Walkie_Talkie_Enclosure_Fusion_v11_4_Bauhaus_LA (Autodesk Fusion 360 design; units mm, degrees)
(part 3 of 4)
sketch "PTT Interaction Field Sketch" plane through (0, 0, 0) normal (1, 0, 0) x axis (0, 0, -1)
  line L1 (-14.65, -17.5) -> (-14.85, -17.5)
  line L2 (-7.85, 34.7) -> (-7.85, -10.7)
  line L3 (-14.85, 41.5) -> (-14.65, 41.5)
  line L4 (-21.65, -10.7) -> (-21.65, 34.7)
  arc A1 centre (-14.65, -10.7) radius 6.8 clockwise from (-7.85, -10.7) to (-14.65, -17.5)
  arc A2 centre (-14.65, 34.7) radius 6.8 clockwise from (-14.65, 41.5) to (-7.85, 34.7)
  arc A3 centre (-14.85, 34.7) radius 6.8 clockwise from (-21.65, 34.7) to (-14.85, 41.5)
  arc A4 centre (-14.85, -10.7) radius 6.8 clockwise from (-14.85, -17.5) to (-21.65, -10.7)
extrude "Extrude7" cut sketch "PTT Interaction Field Sketch" blind -0.42 (= "-( 0.42 mm )") from offset 39.2
sketch "Unified Volume Interaction Field Sketch" plane through (0, 0, 0) normal (1, 0, 0) x axis (0, 0, -1)
  line L1 (-14.65, -21.25) -> (-14.85, -21.25)
  line L2 (-7.85, 31.45) -> (-7.85, -14.45)
  line L3 (-14.85, 38.25) -> (-14.65, 38.25)
  line L4 (-21.65, -14.45) -> (-21.65, 31.45)
  arc A1 centre (-14.65, -14.45) radius 6.8 clockwise from (-7.85, -14.45) to (-14.65, -21.25)
  arc A2 centre (-14.65, 31.45) radius 6.8 clockwise from (-14.65, 38.25) to (-7.85, 31.45)
  arc A3 centre (-14.85, 31.45) radius 6.8 clockwise from (-21.65, 31.45) to (-14.85, 38.25)
  arc A4 centre (-14.85, -14.45) radius 6.8 clockwise from (-14.85, -21.25) to (-21.65, -14.45)
extrude "Extrude8" cut sketch "Unified Volume Interaction Field Sketch" blind 0.42 from offset -39.2
sketch "Left PTT Through Opening Sketch" plane through (0, 0, 0) normal (1, 0, 0) x axis (0, 0, -1)
  line L1 (-14.65, -13.2) -> (-14.85, -13.2)
  line L2 (-10.25, 32.8) -> (-10.25, -8.8)
  line L3 (-14.85, 37.2) -> (-14.65, 37.2)
  line L4 (-19.25, -8.8) -> (-19.25, 32.8)
  arc A1 centre (-14.65, -8.8) radius 4.4 clockwise from (-10.25, -8.8) to (-14.65, -13.2)
  arc A2 centre (-14.65, 32.8) radius 4.4 clockwise from (-14.65, 37.2) to (-10.25, 32.8)
  arc A3 centre (-14.85, 32.8) radius 4.4 clockwise from (-19.25, 32.8) to (-14.85, 37.2)
  arc A4 centre (-14.85, -8.8) radius 4.4 clockwise from (-14.85, -13.2) to (-19.25, -8.8)
extrude "Extrude9" cut sketch "Left PTT Through Opening Sketch" blind 40
sketch "Volume Up Through Opening Sketch" plane through (0, 0, 0) normal (1, 0, 0) x axis (0, 0, -1)
  line L1 (-14.65, 15.15) -> (-14.85, 15.15)
  line L2 (-10.55, 26.75) -> (-10.55, 19.25)
  line L3 (-14.85, 30.85) -> (-14.65, 30.85)
  line L4 (-18.95, 19.25) -> (-18.95, 26.75)
  arc A1 centre (-14.65, 19.25) radius 4.1 clockwise from (-10.55, 19.25) to (-14.65, 15.15)
  arc A2 centre (-14.65, 26.75) radius 4.1 clockwise from (-14.65, 30.85) to (-10.55, 26.75)
  arc A3 centre (-14.85, 26.75) radius 4.1 clockwise from (-18.95, 26.75) to (-14.85, 30.85)
  arc A4 centre (-14.85, 19.25) radius 4.1 clockwise from (-14.85, 15.15) to (-18.95, 19.25)
extrude "Extrude10" cut sketch "Volume Up Through Opening Sketch" blind -40 (= "-( 40.00 mm )")
sketch "Volume Down Through Opening Sketch" plane through (0, 0, 0) normal (1, 0, 0) x axis (0, 0, -1)
  line L1 (-14.65, -13.85) -> (-14.85, -13.85)
  line L2 (-10.55, -2.25) -> (-10.55, -9.75)
  line L3 (-14.85, 1.85) -> (-14.65, 1.85)
  line L4 (-18.95, -9.75) -> (-18.95, -2.25)
  arc A1 centre (-14.65, -9.75) radius 4.1 clockwise from (-10.55, -9.75) to (-14.65, -13.85)
  arc A2 centre (-14.65, -2.25) radius 4.1 clockwise from (-14.65, 1.85) to (-10.55, -2.25)
  arc A3 centre (-14.85, -2.25) radius 4.1 clockwise from (-18.95, -2.25) to (-14.85, 1.85)
  arc A4 centre (-14.85, -9.75) radius 4.1 clockwise from (-14.85, -13.85) to (-18.95, -9.75)
extrude "Extrude11" cut sketch "Volume Down Through Opening Sketch" blind -40 (= "-( 40.00 mm )")
sketch "USB-C Full-Seating Local Wall Recess Sketch" plane through (0, 0, 0) normal (1, 0, 0) x axis (0, 0, -1)
  line L1 (-12.4264, -27.6393) -> (-12.9264, -27.6393)
  line L2 (-8.9764, -17.8393) -> (-8.9764, -24.1893)
  line L3 (-12.9264, -14.3893) -> (-12.4264, -14.3893)
  line L4 (-16.3764, -24.1893) -> (-16.3764, -17.8393)
  arc A1 centre (-12.4264, -24.1893) radius 3.45 clockwise from (-8.9764, -24.1893) to (-12.4264, -27.6393)
  arc A2 centre (-12.4264, -17.8393) radius 3.45 clockwise from (-12.4264, -14.3893) to (-8.9764, -17.8393)
  arc A3 centre (-12.9264, -17.8393) radius 3.45 clockwise from (-16.3764, -17.8393) to (-12.9264, -14.3893)
  arc A4 centre (-12.9264, -24.1893) radius 3.45 clockwise from (-12.9264, -27.6393) to (-16.3764, -24.1893)
extrude "Extrude12" cut sketch "USB-C Full-Seating Local Wall Recess Sketch" blind -2.9527 (= "-( 2.952733 mm )") from offset 39.2
sketch "Sketch13" plane through (0, 0, 0) normal (1, 0, 0) x axis (0, 0, -1)
  line L1 (-12.6264, -25.7043) -> (-12.7264, -25.7043)
  line L2 (-10.2799, -18.6708) -> (-10.2799, -23.3578)
  line L3 (-12.7264, -16.3243) -> (-12.6264, -16.3243)
  line L4 (-15.0729, -23.3578) -> (-15.0729, -18.6708)
  arc A1 centre (-12.6264, -23.3578) radius 2.3465 clockwise from (-10.2799, -23.3578) to (-12.6264, -25.7043)
  arc A2 centre (-12.6264, -18.6708) radius 2.3465 clockwise from (-12.6264, -16.3243) to (-10.2799, -18.6708)
  arc A3 centre (-12.7264, -18.6708) radius 2.3465 clockwise from (-15.0729, -18.6708) to (-12.7264, -16.3243)
  arc A4 centre (-12.7264, -23.3578) radius 2.3465 clockwise from (-12.7264, -25.7043) to (-15.0729, -23.3578)
extrude "Extrude13" cut sketch "Sketch13" blind 40
sketch "PTT Internal Switch Body Clearance Sketch" plane through (0, 0, 0) normal (1, 0, 0) x axis (0, 0, -1)
  line L1 (-10, 6.65) -> (-19.5, 6.65)
  line L2 (-9.55, 16.9) -> (-9.55, 7.1)
  line L3 (-19.5, 17.35) -> (-10, 17.35)
  line L4 (-19.95, 7.1) -> (-19.95, 16.9)
  arc A1 centre (-10, 7.1) radius 0.45 clockwise from (-9.55, 7.1) to (-10, 6.65)
  arc A2 centre (-10, 16.9) radius 0.45 clockwise from (-10, 17.35) to (-9.55, 16.9)
  arc A3 centre (-19.5, 16.9) radius 0.45 clockwise from (-19.95, 16.9) to (-19.5, 17.35)
  arc A4 centre (-19.5, 7.1) radius 0.45 clockwise from (-19.5, 6.65) to (-19.95, 7.1)
extrude "Extrude14" cut sketch "PTT Internal Switch Body Clearance Sketch" blind 5.1 from offset 31.9
sketch "PTT Switch Cage Anchor Sketch" plane through (0, 0, 0) normal (0, 0, 1) x axis (1, 0, 0)
  line L1 (32, 6.45) -> (31.5, 6.45)
  line L2 (32.35, 7.3) -> (32.35, 6.8)
  line L3 (31.5, 7.65) -> (32, 7.65)
  line L4 (31.15, 6.8) -> (31.15, 7.3)
  arc A1 centre (32, 6.8) radius 0.35 clockwise from (32.35, 6.8) to (32, 6.45)
  arc A2 centre (32, 7.3) radius 0.35 clockwise from (32, 7.65) to (32.35, 7.3)
  arc A3 centre (31.5, 7.3) radius 0.35 clockwise from (31.15, 7.3) to (31.5, 7.65)
  arc A4 centre (31.5, 6.8) radius 0.35 clockwise from (31.5, 6.45) to (31.15, 6.8)
extrude "Extrude15" add sketch "PTT Switch Cage Anchor Sketch" blind 7.3 from offset 20.15
sketch "PTT Switch Cage Anchor Sketch (1)" plane through (0, 0, 0) normal (0, 0, 1) x axis (1, 0, 0)
  line L1 (32, 16.35) -> (31.5, 16.35)
  line L2 (32.35, 17.2) -> (32.35, 16.7)
  line L3 (31.5, 17.55) -> (32, 17.55)
  line L4 (31.15, 16.7) -> (31.15, 17.2)
  arc A1 centre (32, 16.7) radius 0.35 clockwise from (32.35, 16.7) to (32, 16.35)
  arc A2 centre (32, 17.2) radius 0.35 clockwise from (32, 17.55) to (32.35, 17.2)
  arc A3 centre (31.5, 17.2) radius 0.35 clockwise from (31.15, 17.2) to (31.5, 17.55)
  arc A4 centre (31.5, 16.7) radius 0.35 clockwise from (31.5, 16.35) to (31.15, 16.7)
extrude "Extrude16" add sketch "PTT Switch Cage Anchor Sketch (1)" blind 7.3 from offset 20.15
sketch "PTT Switch Roof Sketch" plane through (0, 0, 0) normal (0, 0, 1) x axis (1, 0, 0)
  line L1 (36.45, 6.65) -> (31.75, 6.65)
  line L2 (36.9, 16.9) -> (36.9, 7.1)
  line L3 (31.75, 17.35) -> (36.45, 17.35)
  line L4 (31.3, 7.1) -> (31.3, 16.9)
  arc A1 centre (36.45, 7.1) radius 0.45 clockwise from (36.9, 7.1) to (36.45, 6.65)
  arc A2 centre (36.45, 16.9) radius 0.45 clockwise from (36.45, 17.35) to (36.9, 16.9)
  arc A3 centre (31.75, 16.9) radius 0.45 clockwise from (31.3, 16.9) to (31.75, 17.35)
  arc A4 centre (31.75, 7.1) radius 0.45 clockwise from (31.75, 6.65) to (31.3, 7.1)
extrude "Extrude17" add sketch "PTT Switch Roof Sketch" blind 0.55 from offset 19.7
sketch "PTT Switch Inward Backstop Sketch" plane through (0, 0, 0) normal (0, 0, 1) x axis (1, 0, 0)
  line L1 (31.85, 6.65) -> (31.65, 6.65)
  line L2 (32.2, 17) -> (32.2, 7)
  line L3 (31.65, 17.35) -> (31.85, 17.35)
  line L4 (31.3, 7) -> (31.3, 17)
  arc A1 centre (31.85, 7) radius 0.35 clockwise from (32.2, 7) to (31.85, 6.65)
  arc A2 centre (31.85, 17) radius 0.35 clockwise from (31.85, 17.35) to (32.2, 17)
  arc A3 centre (31.65, 17) radius 0.35 clockwise from (31.3, 17) to (31.65, 17.35)
  arc A4 centre (31.65, 7) radius 0.35 clockwise from (31.65, 6.65) to (31.3, 7)
extrude "Extrude18" add sketch "PTT Switch Inward Backstop Sketch" blind 5.25 from offset 15
sketch "PTT Switch Side Rail Sketch" plane through (0, 0, 0) normal (0, 0, 1) x axis (1, 0, 0)
  line L1 (36.675, 6.65) -> (32.325, 6.65)
  line L2 (36.975, 7.15) -> (36.975, 6.95)
  line L3 (32.325, 7.45) -> (36.675, 7.45)
  line L4 (32.025, 6.95) -> (32.025, 7.15)
  arc A1 centre (36.675, 6.95) radius 0.3 clockwise from (36.975, 6.95) to (36.675, 6.65)
  arc A2 centre (36.675, 7.15) radius 0.3 clockwise from (36.675, 7.45) to (36.975, 7.15)
  arc A3 centre (32.325, 7.15) radius 0.3 clockwise from (32.025, 7.15) to (32.325, 7.45)
  arc A4 centre (32.325, 6.95) radius 0.3 clockwise from (32.325, 6.65) to (32.025, 6.95)
extrude "Extrude19" add sketch "PTT Switch Side Rail Sketch" blind 5.25 from offset 15
sketch "PTT Switch Side Rail Sketch (1)" plane through (0, 0, 0) normal (0, 0, 1) x axis (1, 0, 0)
  line L1 (36.675, 16.55) -> (32.325, 16.55)
  line L2 (36.975, 17.05) -> (36.975, 16.85)
  line L3 (32.325, 17.35) -> (36.675, 17.35)
  line L4 (32.025, 16.85) -> (32.025, 17.05)
  arc A1 centre (36.675, 16.85) radius 0.3 clockwise from (36.975, 16.85) to (36.675, 16.55)
  arc A2 centre (36.675, 17.05) radius 0.3 clockwise from (36.675, 17.35) to (36.975, 17.05)
  arc A3 centre (32.325, 17.05) radius 0.3 clockwise from (32.025, 17.05) to (32.325, 17.35)
  arc A4 centre (32.325, 16.85) radius 0.3 clockwise from (32.325, 16.55) to (32.025, 16.85)
extrude "Extrude20" add sketch "PTT Switch Side Rail Sketch (1)" blind 5.25 from offset 15
sketch "PTT Switch Actuator Shoulder Sketch" plane through (0, 0, 0) normal (0, 0, 1) x axis (1, 0, 0)
  line L1 (37.28, 6.65) -> (37.22, 6.65)
  line L2 (37.5, 17.13) -> (37.5, 6.87)
  line L3 (37.22, 17.35) -> (37.28, 17.35)
  line L4 (37, 6.87) -> (37, 17.13)
  arc A1 centre (37.28, 6.87) radius 0.22 clockwise from (37.5, 6.87) to (37.28, 6.65)
  arc A2 centre (37.28, 17.13) radius 0.22 clockwise from (37.28, 17.35) to (37.5, 17.13)
  arc A3 centre (37.22, 17.13) radius 0.22 clockwise from (37, 17.13) to (37.22, 17.35)
  arc A4 centre (37.22, 6.87) radius 0.22 clockwise from (37.22, 6.65) to (37, 6.87)
extrude "Extrude21" add sketch "PTT Switch Actuator Shoulder Sketch" blind 5.25 from offset 15
sketch "PTT Actuator Passage Sketch" plane through (0, 0, 0) normal (1, 0, 0) x axis (0, 0, -1)
  line L1 (-15.9, 10.6) -> (-17.5, 10.6)
  line L2 (-15.3, 12.8) -> (-15.3, 11.2)
  line L3 (-17.5, 13.4) -> (-15.9, 13.4)
  line L4 (-18.1, 11.2) -> (-18.1, 12.8)
  arc A1 centre (-15.9, 11.2) radius 0.6 clockwise from (-15.3, 11.2) to (-15.9, 10.6)
  arc A2 centre (-15.9, 12.8) radius 0.6 clockwise from (-15.9, 13.4) to (-15.3, 12.8)
  arc A3 centre (-17.5, 12.8) radius 0.6 clockwise from (-18.1, 12.8) to (-17.5, 13.4)
  arc A4 centre (-17.5, 11.2) radius 0.6 clockwise from (-17.5, 10.6) to (-18.1, 11.2)
extrude "Extrude22" cut sketch "PTT Actuator Passage Sketch" blind 1.9 from offset 35.8
sketch "Volume Up Internal Switch Body Clearance Sketch" plane through (0, 0, 0) normal (1, 0, 0) x axis (0, 0, -1)
  line L1 (-10, 17.65) -> (-19.5, 17.65)
  line L2 (-9.55, 27.9) -> (-9.55, 18.1)
  line L3 (-19.5, 28.35) -> (-10, 28.35)
  line L4 (-19.95, 18.1) -> (-19.95, 27.9)
  arc A1 centre (-10, 18.1) radius 0.45 clockwise from (-9.55, 18.1) to (-10, 17.65)
  arc A2 centre (-10, 27.9) radius 0.45 clockwise from (-10, 28.35) to (-9.55, 27.9)
  arc A3 centre (-19.5, 27.9) radius 0.45 clockwise from (-19.95, 27.9) to (-19.5, 28.35)
  arc A4 centre (-19.5, 18.1) radius 0.45 clockwise from (-19.5, 17.65) to (-19.95, 18.1)
extrude "Extrude23" cut sketch "Volume Up Internal Switch Body Clearance Sketch" blind -5.1 (= "-( 5.10 mm )") from offset -31.9
sketch "Volume Up Switch Cage Anchor Sketch" plane through (0, 0, 0) normal (0, 0, 1) x axis (1, 0, 0)
  line L1 (-31.5, 17.45) -> (-32, 17.45)
  line L2 (-31.15, 18.3) -> (-31.15, 17.8)
  line L3 (-32, 18.65) -> (-31.5, 18.65)
  line L4 (-32.35, 17.8) -> (-32.35, 18.3)
  arc A1 centre (-31.5, 17.8) radius 0.35 clockwise from (-31.15, 17.8) to (-31.5, 17.45)
  arc A2 centre (-31.5, 18.3) radius 0.35 clockwise from (-31.5, 18.65) to (-31.15, 18.3)
  arc A3 centre (-32, 18.3) radius 0.35 clockwise from (-32.35, 18.3) to (-32, 18.65)
  arc A4 centre (-32, 17.8) radius 0.35 clockwise from (-32, 17.45) to (-32.35, 17.8)
extrude "Extrude24" add sketch "Volume Up Switch Cage Anchor Sketch" blind 7.3 from offset 20.15
sketch "Volume Up Switch Cage Anchor Sketch (1)" plane through (0, 0, 0) normal (0, 0, 1) x axis (1, 0, 0)
  line L1 (-31.5, 27.35) -> (-32, 27.35)
  line L2 (-31.15, 28.2) -> (-31.15, 27.7)
  line L3 (-32, 28.55) -> (-31.5, 28.55)
  line L4 (-32.35, 27.7) -> (-32.35, 28.2)
  arc A1 centre (-31.5, 27.7) radius 0.35 clockwise from (-31.15, 27.7) to (-31.5, 27.35)
  arc A2 centre (-31.5, 28.2) radius 0.35 clockwise from (-31.5, 28.55) to (-31.15, 28.2)
  arc A3 centre (-32, 28.2) radius 0.35 clockwise from (-32.35, 28.2) to (-32, 28.55)
  arc A4 centre (-32, 27.7) radius 0.35 clockwise from (-32, 27.35) to (-32.35, 27.7)
extrude "Extrude25" add sketch "Volume Up Switch Cage Anchor Sketch (1)" blind 7.3 from offset 20.15
sketch "Volume Up Switch Roof Sketch" plane through (0, 0, 0) normal (0, 0, 1) x axis (1, 0, 0)
  line L1 (-31.75, 17.65) -> (-36.45, 17.65)
  line L2 (-31.3, 27.9) -> (-31.3, 18.1)
  line L3 (-36.45, 28.35) -> (-31.75, 28.35)
  line L4 (-36.9, 18.1) -> (-36.9, 27.9)
  arc A1 centre (-31.75, 18.1) radius 0.45 clockwise from (-31.3, 18.1) to (-31.75, 17.65)
  arc A2 centre (-31.75, 27.9) radius 0.45 clockwise from (-31.75, 28.35) to (-31.3, 27.9)
  arc A3 centre (-36.45, 27.9) radius 0.45 clockwise from (-36.9, 27.9) to (-36.45, 28.35)
  arc A4 centre (-36.45, 18.1) radius 0.45 clockwise from (-36.45, 17.65) to (-36.9, 18.1)
extrude "Extrude26" add sketch "Volume Up Switch Roof Sketch" blind 0.55 from offset 19.7
sketch "Volume Up Switch Inward Backstop Sketch" plane through (0, 0, 0) normal (0, 0, 1) x axis (1, 0, 0)
  line L1 (-31.65, 17.65) -> (-31.85, 17.65)
  line L2 (-31.3, 28) -> (-31.3, 18)
  line L3 (-31.85, 28.35) -> (-31.65, 28.35)
  line L4 (-32.2, 18) -> (-32.2, 28)
  arc A1 centre (-31.65, 18) radius 0.35 clockwise from (-31.3, 18) to (-31.65, 17.65)
  arc A2 centre (-31.65, 28) radius 0.35 clockwise from (-31.65, 28.35) to (-31.3, 28)
  arc A3 centre (-31.85, 28) radius 0.35 clockwise from (-32.2, 28) to (-31.85, 28.35)
  arc A4 centre (-31.85, 18) radius 0.35 clockwise from (-31.85, 17.65) to (-32.2, 18)
extrude "Extrude27" add sketch "Volume Up Switch Inward Backstop Sketch" blind 5.25 from offset 15
sketch "Volume Up Switch Side Rail Sketch" plane through (0, 0, 0) normal (0, 0, 1) x axis (1, 0, 0)
  line L1 (-32.325, 17.65) -> (-36.675, 17.65)
  line L2 (-32.025, 18.15) -> (-32.025, 17.95)
  line L3 (-36.675, 18.45) -> (-32.325, 18.45)
  line L4 (-36.975, 17.95) -> (-36.975, 18.15)
  arc A1 centre (-32.325, 17.95) radius 0.3 clockwise from (-32.025, 17.95) to (-32.325, 17.65)
  arc A2 centre (-32.325, 18.15) radius 0.3 clockwise from (-32.325, 18.45) to (-32.025, 18.15)
  arc A3 centre (-36.675, 18.15) radius 0.3 clockwise from (-36.975, 18.15) to (-36.675, 18.45)
  arc A4 centre (-36.675, 17.95) radius 0.3 clockwise from (-36.675, 17.65) to (-36.975, 17.95)
extrude "Extrude28" add sketch "Volume Up Switch Side Rail Sketch" blind 5.25 from offset 15
sketch "Volume Up Switch Side Rail Sketch (1)" plane through (0, 0, 0) normal (0, 0, 1) x axis (1, 0, 0)
  line L1 (-32.325, 27.55) -> (-36.675, 27.55)
  line L2 (-32.025, 28.05) -> (-32.025, 27.85)
  line L3 (-36.675, 28.35) -> (-32.325, 28.35)
  line L4 (-36.975, 27.85) -> (-36.975, 28.05)
  arc A1 centre (-32.325, 27.85) radius 0.3 clockwise from (-32.025, 27.85) to (-32.325, 27.55)
  arc A2 centre (-32.325, 28.05) radius 0.3 clockwise from (-32.325, 28.35) to (-32.025, 28.05)
  arc A3 centre (-36.675, 28.05) radius 0.3 clockwise from (-36.975, 28.05) to (-36.675, 28.35)
  arc A4 centre (-36.675, 27.85) radius 0.3 clockwise from (-36.675, 27.55) to (-36.975, 27.85)
extrude "Extrude29" add sketch "Volume Up Switch Side Rail Sketch (1)" blind 5.25 from offset 15
sketch "Volume Up Switch Actuator Shoulder Sketch" plane through (0, 0, 0) normal (0, 0, 1) x axis (1, 0, 0)
  line L1 (-37.22, 17.65) -> (-37.28, 17.65)
  line L2 (-37, 28.13) -> (-37, 17.87)
  line L3 (-37.28, 28.35) -> (-37.22, 28.35)
  line L4 (-37.5, 17.87) -> (-37.5, 28.13)
  arc A1 centre (-37.22, 17.87) radius 0.22 clockwise from (-37, 17.87) to (-37.22, 17.65)
  arc A2 centre (-37.22, 28.13) radius 0.22 clockwise from (-37.22, 28.35) to (-37, 28.13)
  arc A3 centre (-37.28, 28.13) radius 0.22 clockwise from (-37.5, 28.13) to (-37.28, 28.35)
  arc A4 centre (-37.28, 17.87) radius 0.22 clockwise from (-37.28, 17.65) to (-37.5, 17.87)
extrude "Extrude30" add sketch "Volume Up Switch Actuator Shoulder Sketch" blind 5.25 from offset 15
sketch "Volume Up Actuator Passage Sketch" plane through (0, 0, 0) normal (1, 0, 0) x axis (0, 0, -1)
  line L1 (-15.9, 21.6) -> (-17.5, 21.6)
  line L2 (-15.3, 23.8) -> (-15.3, 22.2)
  line L3 (-17.5, 24.4) -> (-15.9, 24.4)
  line L4 (-18.1, 22.2) -> (-18.1, 23.8)
  arc A1 centre (-15.9, 22.2) radius 0.6 clockwise from (-15.3, 22.2) to (-15.9, 21.6)
  arc A2 centre (-15.9, 23.8) radius 0.6 clockwise from (-15.9, 24.4) to (-15.3, 23.8)
  arc A3 centre (-17.5, 23.8) radius 0.6 clockwise from (-18.1, 23.8) to (-17.5, 24.4)
  arc A4 centre (-17.5, 22.2) radius 0.6 clockwise from (-17.5, 21.6) to (-18.1, 22.2)
extrude "Extrude31" cut sketch "Volume Up Actuator Passage Sketch" blind -1.9 (= "-( 1.90 mm )") from offset -35.8
sketch "Volume Down Internal Switch Body Clearance Sketch" plane through (0, 0, 0) normal (1, 0, 0) x axis (0, 0, -1)
  line L1 (-10, -11.35) -> (-19.5, -11.35)
  line L2 (-9.55, -1.1) -> (-9.55, -10.9)
  line L3 (-19.5, -0.65) -> (-10, -0.65)
  line L4 (-19.95, -10.9) -> (-19.95, -1.1)
  arc A1 centre (-10, -10.9) radius 0.45 clockwise from (-9.55, -10.9) to (-10, -11.35)
  arc A2 centre (-10, -1.1) radius 0.45 clockwise from (-10, -0.65) to (-9.55, -1.1)
  arc A3 centre (-19.5, -1.1) radius 0.45 clockwise from (-19.95, -1.1) to (-19.5, -0.65)
  arc A4 centre (-19.5, -10.9) radius 0.45 clockwise from (-19.5, -11.35) to (-19.95, -10.9)
extrude "Extrude32" cut sketch "Volume Down Internal Switch Body Clearance Sketch" blind -5.1 (= "-( 5.10 mm )") from offset -31.9
sketch "Volume Down Switch Cage Anchor Sketch" plane through (0, 0, 0) normal (0, 0, 1) x axis (1, 0, 0)
  line L1 (-31.5, -11.55) -> (-32, -11.55)
  line L2 (-31.15, -10.7) -> (-31.15, -11.2)
  line L3 (-32, -10.35) -> (-31.5, -10.35)
  line L4 (-32.35, -11.2) -> (-32.35, -10.7)
  arc A1 centre (-31.5, -11.2) radius 0.35 clockwise from (-31.15, -11.2) to (-31.5, -11.55)
  arc A2 centre (-31.5, -10.7) radius 0.35 clockwise from (-31.5, -10.35) to (-31.15, -10.7)
  arc A3 centre (-32, -10.7) radius 0.35 clockwise from (-32.35, -10.7) to (-32, -10.35)
  arc A4 centre (-32, -11.2) radius 0.35 clockwise from (-32, -11.55) to (-32.35, -11.2)
extrude "Extrude33" add sketch "Volume Down Switch Cage Anchor Sketch" blind 7.3 from offset 20.15
sketch "Volume Down Switch Cage Anchor Sketch (1)" plane through (0, 0, 0) normal (0, 0, 1) x axis (1, 0, 0)
  line L1 (-31.5, -1.65) -> (-32, -1.65)
  line L2 (-31.15, -0.8) -> (-31.15, -1.3)
  line L3 (-32, -0.45) -> (-31.5, -0.45)
  line L4 (-32.35, -1.3) -> (-32.35, -0.8)
  arc A1 centre (-31.5, -1.3) radius 0.35 clockwise from (-31.15, -1.3) to (-31.5, -1.65)
  arc A2 centre (-31.5, -0.8) radius 0.35 clockwise from (-31.5, -0.45) to (-31.15, -0.8)
  arc A3 centre (-32, -0.8) radius 0.35 clockwise from (-32.35, -0.8) to (-32, -0.45)
  arc A4 centre (-32, -1.3) radius 0.35 clockwise from (-32, -1.65) to (-32.35, -1.3)
extrude "Extrude34" add sketch "Volume Down Switch Cage Anchor Sketch (1)" blind 7.3 from offset 20.15
sketch "Volume Down Switch Roof Sketch" plane through (0, 0, 0) normal (0, 0, 1) x axis (1, 0, 0)
  line L1 (-31.75, -11.35) -> (-36.45, -11.35)
  line L2 (-31.3, -1.1) -> (-31.3, -10.9)
  line L3 (-36.45, -0.65) -> (-31.75, -0.65)
  line L4 (-36.9, -10.9) -> (-36.9, -1.1)
  arc A1 centre (-31.75, -10.9) radius 0.45 clockwise from (-31.3, -10.9) to (-31.75, -11.35)
  arc A2 centre (-31.75, -1.1) radius 0.45 clockwise from (-31.75, -0.65) to (-31.3, -1.1)
  arc A3 centre (-36.45, -1.1) radius 0.45 clockwise from (-36.9, -1.1) to (-36.45, -0.65)
  arc A4 centre (-36.45, -10.9) radius 0.45 clockwise from (-36.45, -11.35) to (-36.9, -10.9)
extrude "Extrude35" add sketch "Volume Down Switch Roof Sketch" blind 0.55 from offset 19.7
sketch "Volume Down Switch Inward Backstop Sketch" plane through (0, 0, 0) normal (0, 0, 1) x axis (1, 0, 0)
  line L1 (-31.65, -11.35) -> (-31.85, -11.35)
  line L2 (-31.3, -1) -> (-31.3, -11)
  line L3 (-31.85, -0.65) -> (-31.65, -0.65)
  line L4 (-32.2, -11) -> (-32.2, -1)
  arc A1 centre (-31.65, -11) radius 0.35 clockwise from (-31.3, -11) to (-31.65, -11.35)
  arc A2 centre (-31.65, -1) radius 0.35 clockwise from (-31.65, -0.65) to (-31.3, -1)
  arc A3 centre (-31.85, -1) radius 0.35 clockwise from (-32.2, -1) to (-31.85, -0.65)
  arc A4 centre (-31.85, -11) radius 0.35 clockwise from (-31.85, -11.35) to (-32.2, -11)
extrude "Extrude36" add sketch "Volume Down Switch Inward Backstop Sketch" blind 5.25 from offset 15
sketch "Volume Down Switch Side Rail Sketch" plane through (0, 0, 0) normal (0, 0, 1) x axis (1, 0, 0)
  line L1 (-32.325, -11.35) -> (-36.675, -11.35)
  line L2 (-32.025, -10.85) -> (-32.025, -11.05)
  line L3 (-36.675, -10.55) -> (-32.325, -10.55)
  line L4 (-36.975, -11.05) -> (-36.975, -10.85)
  arc A1 centre (-32.325, -11.05) radius 0.3 clockwise from (-32.025, -11.05) to (-32.325, -11.35)
  arc A2 centre (-32.325, -10.85) radius 0.3 clockwise from (-32.325, -10.55) to (-32.025, -10.85)
  arc A3 centre (-36.675, -10.85) radius 0.3 clockwise from (-36.975, -10.85) to (-36.675, -10.55)
  arc A4 centre (-36.675, -11.05) radius 0.3 clockwise from (-36.675, -11.35) to (-36.975, -11.05)
extrude "Extrude37" add sketch "Volume Down Switch Side Rail Sketch" blind 5.25 from offset 15
sketch "Volume Down Switch Side Rail Sketch (1)" plane through (0, 0, 0) normal (0, 0, 1) x axis (1, 0, 0)
  line L1 (-32.325, -1.45) -> (-36.675, -1.45)
  line L2 (-32.025, -0.95) -> (-32.025, -1.15)
  line L3 (-36.675, -0.65) -> (-32.325, -0.65)
  line L4 (-36.975, -1.15) -> (-36.975, -0.95)
  arc A1 centre (-32.325, -1.15) radius 0.3 clockwise from (-32.025, -1.15) to (-32.325, -1.45)
  arc A2 centre (-32.325, -0.95) radius 0.3 clockwise from (-32.325, -0.65) to (-32.025, -0.95)
  arc A3 centre (-36.675, -0.95) radius 0.3 clockwise from (-36.975, -0.95) to (-36.675, -0.65)
  arc A4 centre (-36.675, -1.15) radius 0.3 clockwise from (-36.675, -1.45) to (-36.975, -1.15)
extrude "Extrude38" add sketch "Volume Down Switch Side Rail Sketch (1)" blind 5.25 from offset 15
sketch "Volume Down Switch Actuator Shoulder Sketch" plane through (0, 0, 0) normal (0, 0, 1) x axis (1, 0, 0)
  line L1 (-37.22, -11.35) -> (-37.28, -11.35)
  line L2 (-37, -0.87) -> (-37, -11.13)
  line L3 (-37.28, -0.65) -> (-37.22, -0.65)
  line L4 (-37.5, -11.13) -> (-37.5, -0.87)
  arc A1 centre (-37.22, -11.13) radius 0.22 clockwise from (-37, -11.13) to (-37.22, -11.35)
  arc A2 centre (-37.22, -0.87) radius 0.22 clockwise from (-37.22, -0.65) to (-37, -0.87)
  arc A3 centre (-37.28, -0.87) radius 0.22 clockwise from (-37.5, -0.87) to (-37.28, -0.65)
  arc A4 centre (-37.28, -11.13) radius 0.22 clockwise from (-37.28, -11.35) to (-37.5, -11.13)
extrude "Extrude39" add sketch "Volume Down Switch Actuator Shoulder Sketch" blind 5.25 from offset 15
sketch "Volume Down Actuator Passage Sketch" plane through (0, 0, 0) normal (1, 0, 0) x axis (0, 0, -1)
  line L1 (-15.9, -7.4) -> (-17.5, -7.4)
  line L2 (-15.3, -5.2) -> (-15.3, -6.8)
  line L3 (-17.5, -4.6) -> (-15.9, -4.6)
  line L4 (-18.1, -6.8) -> (-18.1, -5.2)
  arc A1 centre (-15.9, -6.8) radius 0.6 clockwise from (-15.3, -6.8) to (-15.9, -7.4)
  arc A2 centre (-15.9, -5.2) radius 0.6 clockwise from (-15.9, -4.6) to (-15.3, -5.2)
  arc A3 centre (-17.5, -5.2) radius 0.6 clockwise from (-18.1, -5.2) to (-17.5, -4.6)
  arc A4 centre (-17.5, -6.8) radius 0.6 clockwise from (-17.5, -7.4) to (-18.1, -6.8)
extrude "Extrude40" cut sketch "Volume Down Actuator Passage Sketch" blind -1.9 (= "-( 1.90 mm )") from offset -35.8
sketch "PCB Rear Edge Clip Trunk Sketch" plane through (0, 0, 0) normal (0, 0, 1) x axis (1, 0, 0)
  line L1 (-30.95, -25) -> (-31.65, -25)
  line L2 (-30.4, -19.55) -> (-30.4, -24.45)
  line L3 (-31.65, -19) -> (-30.95, -19)
  line L4 (-32.2, -24.45) -> (-32.2, -19.55)
  arc A1 centre (-30.95, -24.45) radius 0.55 clockwise from (-30.4, -24.45) to (-30.95, -25)
  arc A2 centre (-30.95, -19.55) radius 0.55 clockwise from (-30.95, -19) to (-30.4, -19.55)
  arc A3 centre (-31.65, -19.55) radius 0.55 clockwise from (-32.2, -19.55) to (-31.65, -19)
  arc A4 centre (-31.65, -24.45) radius 0.55 clockwise from (-31.65, -25) to (-32.2, -24.45)
extrude "Extrude41" add sketch "PCB Rear Edge Clip Trunk Sketch" blind 15.55 from offset 11.79
sketch "PCB Rear Substrate Ledge Sketch" plane through (0, 0, 0) normal (0, 0, 1) x axis (1, 0, 0)
  line L1 (-28.1, -25) -> (-31, -25)
  line L2 (-27.45, -19.65) -> (-27.45, -24.35)
  line L3 (-31, -19) -> (-28.1, -19)
  line L4 (-31.65, -24.35) -> (-31.65, -19.65)
  arc A1 centre (-28.1, -24.35) radius 0.65 clockwise from (-27.45, -24.35) to (-28.1, -25)
  arc A2 centre (-28.1, -19.65) radius 0.65 clockwise from (-28.1, -19) to (-27.45, -19.65)
  arc A3 centre (-31, -19.65) radius 0.65 clockwise from (-31.65, -19.65) to (-31, -19)
  arc A4 centre (-31, -24.35) radius 0.65 clockwise from (-31, -25) to (-31.65, -24.35)
extrude "Extrude42" add sketch "PCB Rear Substrate Ledge Sketch" blind 0.45 from offset 11.79
sketch "PCB Rear Edge Clip Trunk Sketch (1)" plane through (0, 0, 0) normal (0, 0, 1) x axis (1, 0, 0)
  line L1 (-30.95, 31) -> (-31.65, 31)
  line L2 (-30.4, 36.45) -> (-30.4, 31.55)
  line L3 (-31.65, 37) -> (-30.95, 37)
  line L4 (-32.2, 31.55) -> (-32.2, 36.45)
  arc A1 centre (-30.95, 31.55) radius 0.55 clockwise from (-30.4, 31.55) to (-30.95, 31)
  arc A2 centre (-30.95, 36.45) radius 0.55 clockwise from (-30.95, 37) to (-30.4, 36.45)
  arc A3 centre (-31.65, 36.45) radius 0.55 clockwise from (-32.2, 36.45) to (-31.65, 37)
  arc A4 centre (-31.65, 31.55) radius 0.55 clockwise from (-31.65, 31) to (-32.2, 31.55)
extrude "Extrude43" add sketch "PCB Rear Edge Clip Trunk Sketch (1)" blind 15.55 from offset 11.79
sketch "PCB Rear Substrate Ledge Sketch (1)" plane through (0, 0, 0) normal (0, 0, 1) x axis (1, 0, 0)
  line L1 (-28.1, 31) -> (-31, 31)
  line L2 (-27.45, 36.35) -> (-27.45, 31.65)
  line L3 (-31, 37) -> (-28.1, 37)
  line L4 (-31.65, 31.65) -> (-31.65, 36.35)
  arc A1 centre (-28.1, 31.65) radius 0.65 clockwise from (-27.45, 31.65) to (-28.1, 31)
  arc A2 centre (-28.1, 36.35) radius 0.65 clockwise from (-28.1, 37) to (-27.45, 36.35)
  arc A3 centre (-31, 36.35) radius 0.65 clockwise from (-31.65, 36.35) to (-31, 37)
  arc A4 centre (-31, 31.65) radius 0.65 clockwise from (-31, 31) to (-31.65, 31.65)
extrude "Extrude44" add sketch "PCB Rear Substrate Ledge Sketch (1)" blind 0.45 from offset 11.79
sketch "PCB Rear Edge Clip Trunk Sketch (2)" plane through (0, 0, 0) normal (0, 0, 1) x axis (1, 0, 0)
  line L1 (31.65, -25) -> (30.95, -25)
  line L2 (32.2, -19.55) -> (32.2, -24.45)
  line L3 (30.95, -19) -> (31.65, -19)
  line L4 (30.4, -24.45) -> (30.4, -19.55)
  arc A1 centre (31.65, -24.45) radius 0.55 clockwise from (32.2, -24.45) to (31.65, -25)
  arc A2 centre (31.65, -19.55) radius 0.55 clockwise from (31.65, -19) to (32.2, -19.55)
  arc A3 centre (30.95, -19.55) radius 0.55 clockwise from (30.4, -19.55) to (30.95, -19)
  arc A4 centre (30.95, -24.45) radius 0.55 clockwise from (30.95, -25) to (30.4, -24.45)
extrude "Extrude45" add sketch "PCB Rear Edge Clip Trunk Sketch (2)" blind 15.55 from offset 11.79
sketch "PCB Rear Substrate Ledge Sketch (2)" plane through (0, 0, 0) normal (0, 0, 1) x axis (1, 0, 0)
  line L1 (31, -25) -> (28.1, -25)
  line L2 (31.65, -19.65) -> (31.65, -24.35)
  line L3 (28.1, -19) -> (31, -19)
  line L4 (27.45, -24.35) -> (27.45, -19.65)
  arc A1 centre (31, -24.35) radius 0.65 clockwise from (31.65, -24.35) to (31, -25)
  arc A2 centre (31, -19.65) radius 0.65 clockwise from (31, -19) to (31.65, -19.65)
  arc A3 centre (28.1, -19.65) radius 0.65 clockwise from (27.45, -19.65) to (28.1, -19)
  arc A4 centre (28.1, -24.35) radius 0.65 clockwise from (28.1, -25) to (27.45, -24.35)
extrude "Extrude46" add sketch "PCB Rear Substrate Ledge Sketch (2)" blind 0.45 from offset 11.79
sketch "PCB Rear Edge Clip Trunk Sketch (3)" plane through (0, 0, 0) normal (0, 0, 1) x axis (1, 0, 0)
  line L1 (31.65, 31) -> (30.95, 31)
  line L2 (32.2, 36.45) -> (32.2, 31.55)
  line L3 (30.95, 37) -> (31.65, 37)
  line L4 (30.4, 31.55) -> (30.4, 36.45)
  arc A1 centre (31.65, 31.55) radius 0.55 clockwise from (32.2, 31.55) to (31.65, 31)
  arc A2 centre (31.65, 36.45) radius 0.55 clockwise from (31.65, 37) to (32.2, 36.45)
  arc A3 centre (30.95, 36.45) radius 0.55 clockwise from (30.4, 36.45) to (30.95, 37)
  arc A4 centre (30.95, 31.55) radius 0.55 clockwise from (30.95, 31) to (30.4, 31.55)
extrude "Extrude47" add sketch "PCB Rear Edge Clip Trunk Sketch (3)" blind 15.55 from offset 11.79
sketch "PCB Rear Substrate Ledge Sketch (3)" plane through (0, 0, 0) normal (0, 0, 1) x axis (1, 0, 0)
  line L1 (31, 31) -> (28.1, 31)
  line L2 (31.65, 36.35) -> (31.65, 31.65)
  line L3 (28.1, 37) -> (31, 37)
  line L4 (27.45, 31.65) -> (27.45, 36.35)
  arc A1 centre (31, 31.65) radius 0.65 clockwise from (31.65, 31.65) to (31, 31)
  arc A2 centre (31, 36.35) radius 0.65 clockwise from (31, 37) to (31.65, 36.35)
  arc A3 centre (28.1, 36.35) radius 0.65 clockwise from (27.45, 36.35) to (28.1, 37)
  arc A4 centre (28.1, 31.65) radius 0.65 clockwise from (28.1, 31) to (27.45, 31.65)
extrude "Extrude48" add sketch "PCB Rear Substrate Ledge Sketch (3)" blind 0.45 from offset 11.79
sketch "Battery Cradle Left Side Rail Sketch" plane through (0, 0, 0) normal (0, 0, 1) x axis (1, 0, 0)
  line L1 (-30.86, -62.76) -> (-31.06, -62.76)
  line L2 (-30.26, -26.84) -> (-30.26, -62.16)
  line L3 (-31.06, -26.24) -> (-30.86, -26.24)
  line L4 (-31.66, -62.16) -> (-31.66, -26.84)
  arc A1 centre (-30.86, -62.16) radius 0.6 clockwise from (-30.26, -62.16) to (-30.86, -62.76)
  arc A2 centre (-30.86, -26.84) radius 0.6 clockwise from (-30.86, -26.24) to (-30.26, -26.84)
  arc A3 centre (-31.06, -26.84) radius 0.6 clockwise from (-31.66, -26.84) to (-31.06, -26.24)
  arc A4 centre (-31.06, -62.16) radius 0.6 clockwise from (-31.06, -62.76) to (-31.66, -62.16)
extrude "Extrude49" new body sketch "Battery Cradle Left Side Rail Sketch" blind 3.3 from offset 17.5
sketch "Battery +X Lead-Relieved Side Rail Sketch" plane through (0, 0, 0) normal (0, 0, 1) x axis (1, 0, 0)
  line L1 (31.06, -62.76) -> (30.86, -62.76)
  line L2 (31.66, -47.75) -> (31.66, -62.16)
  line L3 (30.86, -47.15) -> (31.06, -47.15)
  line L4 (30.26, -62.16) -> (30.26, -47.75)
  arc A1 centre (31.06, -62.16) radius 0.6 clockwise from (31.66, -62.16) to (31.06, -62.76)
  arc A2 centre (31.06, -47.75) radius 0.6 clockwise from (31.06, -47.15) to (31.66, -47.75)
  arc A3 centre (30.86, -47.75) radius 0.6 clockwise from (30.26, -47.75) to (30.86, -47.15)
  arc A4 centre (30.86, -62.16) radius 0.6 clockwise from (30.86, -62.76) to (30.26, -62.16)
extrude "Extrude50" new body sketch "Battery +X Lead-Relieved Side Rail Sketch" blind 3.3 from offset 17.5
sketch "Battery +X Lead-Relieved Side Rail Sketch (1)" plane through (0, 0, 0) normal (0, 0, 1) x axis (1, 0, 0)
  line L1 (31.06, -41.85) -> (30.86, -41.85)
  line L2 (31.66, -26.84) -> (31.66, -41.25)
  line L3 (30.86, -26.24) -> (31.06, -26.24)
  line L4 (30.26, -41.25) -> (30.26, -26.84)
  arc A1 centre (31.06, -41.25) radius 0.6 clockwise from (31.66, -41.25) to (31.06, -41.85)
  arc A2 centre (31.06, -26.84) radius 0.6 clockwise from (31.06, -26.24) to (31.66, -26.84)
  arc A3 centre (30.86, -26.84) radius 0.6 clockwise from (30.26, -26.84) to (30.86, -26.24)
  arc A4 centre (30.86, -41.25) radius 0.6 clockwise from (30.86, -41.85) to (30.26, -41.25)
extrude "Extrude51" new body sketch "Battery +X Lead-Relieved Side Rail Sketch (1)" blind 3.3 from offset 17.5
sketch "Battery Cradle Bottom Rail Sketch" plane through (0, 0, 0) normal (0, 0, 1) x axis (1, 0, 0)
  line L1 (31.2, -64.16) -> (-31.2, -64.16)
  line L2 (31.8, -63.36) -> (31.8, -63.56)
  line L3 (-31.2, -62.76) -> (31.2, -62.76)
  line L4 (-31.8, -63.56) -> (-31.8, -63.36)
  arc A1 centre (31.2, -63.56) radius 0.6 clockwise from (31.8, -63.56) to (31.2, -64.16)
  arc A2 centre (31.2, -63.36) radius 0.6 clockwise from (31.2, -62.76) to (31.8, -63.36)
  arc A3 centre (-31.2, -63.36) radius 0.6 clockwise from (-31.8, -63.36) to (-31.2, -62.76)
  arc A4 centre (-31.2, -63.56) radius 0.6 clockwise from (-31.2, -64.16) to (-31.8, -63.56)
extrude "Extrude52" add sketch "Battery Cradle Bottom Rail Sketch" blind 3.3 from offset 17.5
sketch "Battery Cradle Top Rail Sketch" plane through (0, 0, 0) normal (0, 0, 1) x axis (1, 0, 0)
  line L1 (31.2, -26.24) -> (-31.2, -26.24)
  line L2 (31.8, -25.44) -> (31.8, -25.64)
  line L3 (-31.2, -24.84) -> (31.2, -24.84)
  line L4 (-31.8, -25.64) -> (-31.8, -25.44)
  arc A1 centre (31.2, -25.64) radius 0.6 clockwise from (31.8, -25.64) to (31.2, -26.24)
  arc A2 centre (31.2, -25.44) radius 0.6 clockwise from (31.2, -24.84) to (31.8, -25.44)
  arc A3 centre (-31.2, -25.44) radius 0.6 clockwise from (-31.8, -25.44) to (-31.2, -24.84)
  arc A4 centre (-31.2, -25.64) radius 0.6 clockwise from (-31.2, -26.24) to (-31.8, -25.64)
extrude "Extrude53" add sketch "Battery Cradle Top Rail Sketch" blind 3.3 from offset 17.5
sketch "Battery Rounded Front Support Sketch" plane through (0, 0, 0) normal (0, 0, 1) x axis (1, 0, 0)
  line L1 (-27.1, -48.5) -> (-30.5, -48.5)
  line L2 (-26.1, -41.5) -> (-26.1, -47.5)
  line L3 (-30.5, -40.5) -> (-27.1, -40.5)
  line L4 (-31.5, -47.5) -> (-31.5, -41.5)
  arc A1 centre (-27.1, -47.5) radius 1 clockwise from (-26.1, -47.5) to (-27.1, -48.5)
  arc A2 centre (-27.1, -41.5) radius 1 clockwise from (-27.1, -40.5) to (-26.1, -41.5)
  arc A3 centre (-30.5, -41.5) radius 1 clockwise from (-31.5, -41.5) to (-30.5, -40.5)
  arc A4 centre (-30.5, -47.5) radius 1 clockwise from (-30.5, -48.5) to (-31.5, -47.5)
extrude "Extrude54" add sketch "Battery Rounded Front Support Sketch" blind 0.44 from offset 17.1
sketch "Battery Rounded Front Support Sketch (1)" plane through (0, 0, 0) normal (0, 0, 1) x axis (1, 0, 0)
  line L1 (30.5, -48.5) -> (27.1, -48.5)
  line L2 (31.5, -41.5) -> (31.5, -47.5)
  line L3 (27.1, -40.5) -> (30.5, -40.5)
  line L4 (26.1, -47.5) -> (26.1, -41.5)
  arc A1 centre (30.5, -47.5) radius 1 clockwise from (31.5, -47.5) to (30.5, -48.5)
  arc A2 centre (30.5, -41.5) radius 1 clockwise from (30.5, -40.5) to (31.5, -41.5)
  arc A3 centre (27.1, -41.5) radius 1 clockwise from (26.1, -41.5) to (27.1, -40.5)
  arc A4 centre (27.1, -47.5) radius 1 clockwise from (27.1, -48.5) to (26.1, -47.5)
extrude "Extrude55" add sketch "Battery Rounded Front Support Sketch (1)" blind 0.44 from offset 17.1
sketch "Battery Broad Rear Retention Pad Sketch" plane through (0, 0, 0) normal (0, 0, 1) x axis (1, 0, 0)
  line L1 (-9, -48.5) -> (-19, -48.5)
  line L2 (-7, -42.5) -> (-7, -46.5)
  line L3 (-19, -40.5) -> (-9, -40.5)
  line L4 (-21, -46.5) -> (-21, -42.5)
  arc A1 centre (-9, -46.5) radius 2 clockwise from (-7, -46.5) to (-9, -48.5)
  arc A2 centre (-9, -42.5) radius 2 clockwise from (-9, -40.5) to (-7, -42.5)
  arc A3 centre (-19, -42.5) radius 2 clockwise from (-21, -42.5) to (-19, -40.5)
  arc A4 centre (-19, -46.5) radius 2 clockwise from (-19, -48.5) to (-21, -46.5)
extrude "Extrude56" add sketch "Battery Broad Rear Retention Pad Sketch" blind 0.84 from offset 26.46
sketch "Battery Broad Rear Retention Pad Sketch (1)" plane through (0, 0, 0) normal (0, 0, 1) x axis (1, 0, 0)
  line L1 (19, -48.5) -> (9, -48.5)
  line L2 (21, -42.5) -> (21, -46.5)
  line L3 (9, -40.5) -> (19, -40.5)
  line L4 (7, -46.5) -> (7, -42.5)
  arc A1 centre (19, -46.5) radius 2 clockwise from (21, -46.5) to (19, -48.5)
  arc A2 centre (19, -42.5) radius 2 clockwise from (19, -40.5) to (21, -42.5)
  arc A3 centre (9, -42.5) radius 2 clockwise from (7, -42.5) to (9, -40.5)
  arc A4 centre (9, -46.5) radius 2 clockwise from (9, -48.5) to (7, -46.5)
extrude "Extrude57" add sketch "Battery Broad Rear Retention Pad Sketch (1)" blind 0.84 from offset 26.46
sketch "LTE Antenna Locator Rail Sketch" plane through (0, 0, 0) normal (0, 0, 1) x axis (1, 0, 0)
  line L1 (-11.16, -34.76) -> (-11.26, -34.76)
  line L2 (-10.76, 67.36) -> (-10.76, -34.36)
  line L3 (-11.26, 67.76) -> (-11.16, 67.76)
  line L4 (-11.66, -34.36) -> (-11.66, 67.36)
  arc A1 centre (-11.16, -34.36) radius 0.4 clockwise from (-10.76, -34.36) to (-11.16, -34.76)
  arc A2 centre (-11.16, 67.36) radius 0.4 clockwise from (-11.16, 67.76) to (-10.76, 67.36)
  arc A3 centre (-11.26, 67.36) radius 0.4 clockwise from (-11.66, 67.36) to (-11.26, 67.76)
  arc A4 centre (-11.26, -34.36) radius 0.4 clockwise from (-11.26, -34.76) to (-11.66, -34.36)
extrude "Extrude58" add sketch "LTE Antenna Locator Rail Sketch" blind 1.25 from offset 26.05
sketch "LTE Antenna Locator Rail Sketch (1)" plane through (0, 0, 0) normal (0, 0, 1) x axis (1, 0, 0)
  line L1 (11.26, -34.76) -> (11.16, -34.76)
  line L2 (11.66, 67.36) -> (11.66, -34.36)
  line L3 (11.16, 67.76) -> (11.26, 67.76)
  line L4 (10.76, -34.36) -> (10.76, 67.36)
  arc A1 centre (11.26, -34.36) radius 0.4 clockwise from (11.66, -34.36) to (11.26, -34.76)
  arc A2 centre (11.26, 67.36) radius 0.4 clockwise from (11.26, 67.76) to (11.66, 67.36)
  arc A3 centre (11.16, 67.36) radius 0.4 clockwise from (10.76, 67.36) to (11.16, 67.76)
  arc A4 centre (11.16, -34.36) radius 0.4 clockwise from (11.16, -34.76) to (10.76, -34.36)
extrude "Extrude59" add sketch "LTE Antenna Locator Rail Sketch (1)" blind 1.25 from offset 26.05
sketch "LTE Antenna Lower End Stop Sketch" plane through (0, 0, 0) normal (0, 0, 1) x axis (1, 0, 0)
  line L1 (11.1, -35.66) -> (-11.1, -35.66)
  line L2 (11.5, -35.16) -> (11.5, -35.26)
  line L3 (-11.1, -34.76) -> (11.1, -34.76)
  line L4 (-11.5, -35.26) -> (-11.5, -35.16)
  arc A1 centre (11.1, -35.26) radius 0.4 clockwise from (11.5, -35.26) to (11.1, -35.66)
  arc A2 centre (11.1, -35.16) radius 0.4 clockwise from (11.1, -34.76) to (11.5, -35.16)
  arc A3 centre (-11.1, -35.16) radius 0.4 clockwise from (-11.5, -35.16) to (-11.1, -34.76)
  arc A4 centre (-11.1, -35.26) radius 0.4 clockwise from (-11.1, -35.66) to (-11.5, -35.26)
extrude "Extrude60" add sketch "LTE Antenna Lower End Stop Sketch" blind 1.25 from offset 26.05
sketch "Sketch61" plane through (0, 0, 0) normal (0, 0, 1) x axis (1, 0, 0)
  line L1 (-5.4, 67.76) -> (-11.1, 67.76)
  line L2 (-5, 68.26) -> (-5, 68.16)
  line L3 (-11.1, 68.66) -> (-5.4, 68.66)
  line L4 (-11.5, 68.16) -> (-11.5, 68.26)
  arc A1 centre (-5.4, 68.16) radius 0.4 clockwise from (-5, 68.16) to (-5.4, 67.76)
  arc A2 centre (-5.4, 68.26) radius 0.4 clockwise from (-5.4, 68.66) to (-5, 68.26)
  arc A3 centre (-11.1, 68.26) radius 0.4 clockwise from (-11.5, 68.26) to (-11.1, 68.66)
  arc A4 centre (-11.1, 68.16) radius 0.4 clockwise from (-11.1, 67.76) to (-11.5, 68.16)
extrude "Extrude61" add sketch "Sketch61" blind 1.25 from offset 26.05
sketch "Sketch62" plane through (0, 0, 0) normal (0, 0, 1) x axis (1, 0, 0)
  line L1 (11.1, 67.76) -> (5.4, 67.76)
  line L2 (11.5, 68.26) -> (11.5, 68.16)
  line L3 (5.4, 68.66) -> (11.1, 68.66)
  line L4 (5, 68.16) -> (5, 68.26)
  arc A1 centre (11.1, 68.16) radius 0.4 clockwise from (11.5, 68.16) to (11.1, 67.76)
  arc A2 centre (11.1, 68.26) radius 0.4 clockwise from (11.1, 68.66) to (11.5, 68.26)
  arc A3 centre (5.4, 68.26) radius 0.4 clockwise from (5, 68.26) to (5.4, 68.66)
  arc A4 centre (5.4, 68.16) radius 0.4 clockwise from (5.4, 67.76) to (5, 68.16)
extrude "Extrude62" add sketch "Sketch62" blind 1.25 from offset 26.05
sketch "LTE Antenna Front Capture Lip Sketch" plane through (0, 0, 0) normal (0, 0, 1) x axis (1, 0, 0)
  line L1 (-9.85, -22) -> (-10.95, -22)
  line L2 (-9.4, -18.45) -> (-9.4, -21.55)
  line L3 (-10.95, -18) -> (-9.85, -18)
  line L4 (-11.4, -21.55) -> (-11.4, -18.45)
  arc A1 centre (-9.85, -21.55) radius 0.45 clockwise from (-9.4, -21.55) to (-9.85, -22)
  arc A2 centre (-9.85, -18.45) radius 0.45 clockwise from (-9.85, -18) to (-9.4, -18.45)
  arc A3 centre (-10.95, -18.45) radius 0.45 clockwise from (-11.4, -18.45) to (-10.95, -18)
  arc A4 centre (-10.95, -21.55) radius 0.45 clockwise from (-10.95, -22) to (-11.4, -21.55)
extrude "Extrude63" add sketch "LTE Antenna Front Capture Lip Sketch" blind 0.2 from offset 26.04
sketch "LTE Antenna Front Capture Lip Sketch (1)" plane through (0, 0, 0) normal (0, 0, 1) x axis (1, 0, 0)
  line L1 (-9.85, 51) -> (-10.95, 51)
  line L2 (-9.4, 54.55) -> (-9.4, 51.45)
  line L3 (-10.95, 55) -> (-9.85, 55)
  line L4 (-11.4, 51.45) -> (-11.4, 54.55)
  arc A1 centre (-9.85, 51.45) radius 0.45 clockwise from (-9.4, 51.45) to (-9.85, 51)
  arc A2 centre (-9.85, 54.55) radius 0.45 clockwise from (-9.85, 55) to (-9.4, 54.55)
  arc A3 centre (-10.95, 54.55) radius 0.45 clockwise from (-11.4, 54.55) to (-10.95, 55)
  arc A4 centre (-10.95, 51.45) radius 0.45 clockwise from (-10.95, 51) to (-11.4, 51.45)
extrude "Extrude64" add sketch "LTE Antenna Front Capture Lip Sketch (1)" blind 0.2 from offset 26.04
sketch "LTE Antenna Front Capture Lip Sketch (2)" plane through (0, 0, 0) normal (0, 0, 1) x axis (1, 0, 0)
  line L1 (10.95, -22) -> (9.85, -22)
  line L2 (11.4, -18.45) -> (11.4, -21.55)
  line L3 (9.85, -18) -> (10.95, -18)
  line L4 (9.4, -21.55) -> (9.4, -18.45)
  arc A1 centre (10.95, -21.55) radius 0.45 clockwise from (11.4, -21.55) to (10.95, -22)
  arc A2 centre (10.95, -18.45) radius 0.45 clockwise from (10.95, -18) to (11.4, -18.45)
  arc A3 centre (9.85, -18.45) radius 0.45 clockwise from (9.4, -18.45) to (9.85, -18)
  arc A4 centre (9.85, -21.55) radius 0.45 clockwise from (9.85, -22) to (9.4, -21.55)
extrude "Extrude65" add sketch "LTE Antenna Front Capture Lip Sketch (2)" blind 0.2 from offset 26.04
sketch "LTE Antenna Front Capture Lip Sketch (3)" plane through (0, 0, 0) normal (0, 0, 1) x axis (1, 0, 0)
  line L1 (10.95, 51) -> (9.85, 51)
  line L2 (11.4, 54.55) -> (11.4, 51.45)
  line L3 (9.85, 55) -> (10.95, 55)
  line L4 (9.4, 51.45) -> (9.4, 54.55)
  arc A1 centre (10.95, 51.45) radius 0.45 clockwise from (11.4, 51.45) to (10.95, 51)
  arc A2 centre (10.95, 54.55) radius 0.45 clockwise from (10.95, 55) to (11.4, 54.55)
  arc A3 centre (9.85, 54.55) radius 0.45 clockwise from (9.4, 54.55) to (9.85, 55)
  arc A4 centre (9.85, 51.45) radius 0.45 clockwise from (9.85, 51) to (9.4, 51.45)
extrude "Extrude66" add sketch "LTE Antenna Front Capture Lip Sketch (3)" blind 0.2 from offset 26.04
sketch "LTE Antenna Rear Land Sketch" plane through (0, 0, 0) normal (0, 0, 1) x axis (1, 0, 0)
  line L1 (-8.45, -22) -> (-9.55, -22)
  line L2 (-8, -18.45) -> (-8, -21.55)
  line L3 (-9.55, -18) -> (-8.45, -18)
  line L4 (-10, -21.55) -> (-10, -18.45)
  arc A1 centre (-8.45, -21.55) radius 0.45 clockwise from (-8, -21.55) to (-8.45, -22)
  arc A2 centre (-8.45, -18.45) radius 0.45 clockwise from (-8.45, -18) to (-8, -18.45)
  arc A3 centre (-9.55, -18.45) radius 0.45 clockwise from (-10, -18.45) to (-9.55, -18)
  arc A4 centre (-9.55, -21.55) radius 0.45 clockwise from (-9.55, -22) to (-10, -21.55)
extrude "Extrude67" add sketch "LTE Antenna Rear Land Sketch" blind 0.19 from offset 27.11
sketch "LTE Antenna Rear Land Sketch (1)" plane through (0, 0, 0) normal (0, 0, 1) x axis (1, 0, 0)
  line L1 (-8.45, 51) -> (-9.55, 51)
  line L2 (-8, 54.55) -> (-8, 51.45)
  line L3 (-9.55, 55) -> (-8.45, 55)
  line L4 (-10, 51.45) -> (-10, 54.55)
  arc A1 centre (-8.45, 51.45) radius 0.45 clockwise from (-8, 51.45) to (-8.45, 51)
  arc A2 centre (-8.45, 54.55) radius 0.45 clockwise from (-8.45, 55) to (-8, 54.55)
  arc A3 centre (-9.55, 54.55) radius 0.45 clockwise from (-10, 54.55) to (-9.55, 55)
  arc A4 centre (-9.55, 51.45) radius 0.45 clockwise from (-9.55, 51) to (-10, 51.45)
extrude "Extrude68" add sketch "LTE Antenna Rear Land Sketch (1)" blind 0.19 from offset 27.11
sketch "LTE Antenna Rear Land Sketch (2)" plane through (0, 0, 0) normal (0, 0, 1) x axis (1, 0, 0)
  line L1 (9.55, -22) -> (8.45, -22)
  line L2 (10, -18.45) -> (10, -21.55)
  line L3 (8.45, -18) -> (9.55, -18)
  line L4 (8, -21.55) -> (8, -18.45)
  arc A1 centre (9.55, -21.55) radius 0.45 clockwise from (10, -21.55) to (9.55, -22)
  arc A2 centre (9.55, -18.45) radius 0.45 clockwise from (9.55, -18) to (10, -18.45)
  arc A3 centre (8.45, -18.45) radius 0.45 clockwise from (8, -18.45) to (8.45, -18)
  arc A4 centre (8.45, -21.55) radius 0.45 clockwise from (8.45, -22) to (8, -21.55)
extrude "Extrude69" add sketch "LTE Antenna Rear Land Sketch (2)" blind 0.19 from offset 27.11
sketch "LTE Antenna Rear Land Sketch (3)" plane through (0, 0, 0) normal (0, 0, 1) x axis (1, 0, 0)
  line L1 (9.55, 51) -> (8.45, 51)
  line L2 (10, 54.55) -> (10, 51.45)
  line L3 (8.45, 55) -> (9.55, 55)
  line L4 (8, 51.45) -> (8, 54.55)
  arc A1 centre (9.55, 51.45) radius 0.45 clockwise from (10, 51.45) to (9.55, 51)
  arc A2 centre (9.55, 54.55) radius 0.45 clockwise from (9.55, 55) to (10, 54.55)
  arc A3 centre (8.45, 54.55) radius 0.45 clockwise from (8, 54.55) to (8.45, 55)
  arc A4 centre (8.45, 51.45) radius 0.45 clockwise from (8.45, 51) to (8, 51.45)
extrude "Extrude70" add sketch "LTE Antenna Rear Land Sketch (3)" blind 0.19 from offset 27.11
sketch "Rear Screw Bosses" plane through (0, 0, 0) normal (0, 0, 1) x axis (1, 0, 0)
  circle C1 centre (-33.4, -56) radius 2.8
  circle C2 centre (-33.4, 56) radius 2.8
  circle C3 centre (33.4, -56) radius 2.8
  circle C4 centre (33.4, 56) radius 2.8
extrude "Extrude71" add sketch "Rear Screw Bosses" blind 4.5 from offset 15
sketch "M2.5 Screw Clearances" plane through (0, 0, 0) normal (0, 0, 1) x axis (1, 0, 0)
  circle C1 centre (-33.4, -56) radius 1.45
  circle C2 centre (-33.4, 56) radius 1.45
  circle C3 centre (33.4, -56) radius 1.45
  circle C4 centre (33.4, 56) radius 1.45
extrude "Extrude72" cut sketch "M2.5 Screw Clearances" blind 15.5 from offset 14.5
sketch "Rear Screw Counterbores" plane through (0, 0, 0) normal (0, 0, 1) x axis (1, 0, 0)
  circle C1 centre (-33.4, -56) radius 2.55
  circle C2 centre (-33.4, 56) radius 2.55
  circle C3 centre (33.4, -56) radius 2.55
  circle C4 centre (33.4, 56) radius 2.55
extrude "Extrude73" cut sketch "Rear Screw Counterbores" blind 3.3 from offset 26.7
sketch "Quiet Orb Action Button Cap Sketch" plane through (0, 0, 0) normal (0, 0, 1) x axis (1, 0, 0)
  line L1 (4.4, -60.7) -> (-4.4, -60.7)
  line L2 (13.7, -42.6) -> (13.7, -51.4)
  line L3 (-4.4, -33.3) -> (4.4, -33.3)
  line L4 (-13.7, -51.4) -> (-13.7, -42.6)
  arc A1 centre (4.4, -51.4) radius 9.3 clockwise from (13.7, -51.4) to (4.4, -60.7)
  arc A2 centre (4.4, -42.6) radius 9.3 clockwise from (4.4, -33.3) to (13.7, -42.6)
  arc A3 centre (-4.4, -42.6) radius 9.3 clockwise from (-13.7, -42.6) to (-4.4, -33.3)
  arc A4 centre (-4.4, -51.4) radius 9.3 clockwise from (-4.4, -60.7) to (-13.7, -51.4)
extrude "Extrude1" new body sketch "Quiet Orb Action Button Cap Sketch" blind 2.95 from offset -0.55
fillet "Fillet1" radius 1.35
sketch "Action Button Guide Ring" plane through (0, 0, 0) normal (0, 0, 1) x axis (1, 0, 0)
  line L1 (4.3, -60.5) -> (-4.3, -60.5)
  line L2 (13.5, -42.7) -> (13.5, -51.3)
  line L3 (-4.3, -33.5) -> (4.3, -33.5)
  line L4 (-13.5, -51.3) -> (-13.5, -42.7)
  line L5 (4.55, -58.8) -> (-4.55, -58.8)
  line L6 (11.8, -42.45) -> (11.8, -51.55)
  line L7 (-4.55, -35.2) -> (4.55, -35.2)
  line L8 (-11.8, -51.55) -> (-11.8, -42.45)
  arc A1 centre (4.3, -51.3) radius 9.2 clockwise from (13.5, -51.3) to (4.3, -60.5)
  arc A2 centre (4.3, -42.7) radius 9.2 clockwise from (4.3, -33.5) to (13.5, -42.7)
  arc A3 centre (-4.3, -42.7) radius 9.2 clockwise from (-13.5, -42.7) to (-4.3, -33.5)
  arc A4 centre (-4.3, -51.3) radius 9.2 clockwise from (-4.3, -60.5) to (-13.5, -51.3)
  arc A5 centre (4.55, -51.55) radius 7.25 clockwise from (11.8, -51.55) to (4.55, -58.8)
  arc A6 centre (4.55, -42.45) radius 7.25 clockwise from (4.55, -35.2) to (11.8, -42.45)
  arc A7 centre (-4.55, -42.45) radius 7.25 clockwise from (-11.8, -42.45) to (-4.55, -35.2)
  arc A8 centre (-4.55, -51.55) radius 7.25 clockwise from (-4.55, -58.8) to (-11.8, -51.55)
extrude "Extrude2" add sketch "Action Button Guide Ring" blind 0.5 from offset 2.05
